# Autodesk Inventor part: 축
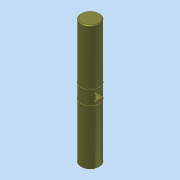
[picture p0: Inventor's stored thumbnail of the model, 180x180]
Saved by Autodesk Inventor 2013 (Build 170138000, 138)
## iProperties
Company: 한국ATC센터
Created: 2015-04
Part Number: 축
Document SubType Name: Modeling
Designer: KYOUNG IL JANG
Density: 7.85 g/cm^3
Material: 강
Author: KYOUNG IL JANG
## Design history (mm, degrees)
sketch "스케치1"
  geometry: C1 r 11 at (0, 0); 1 further point
  constraints: 1 centre point, 1 coincident
  dimensions: "d0" = 22 diameter of C1
extrude "돌출1" new body sketch "스케치1" stored distance "d1" = 150; taper "d2" = 0 deg
sketch "스케치2"
  geometry: L1 (-10.247, -4)-(10.247, -4); L2 (-10.247, 4)-(10.247, 4); A1 r 11 centre (0, 0) between (-10.247, -4) and (10.247, -4) reference; 1 further point
  constraints: 4 end point, 4 point on circle, 2 parallel, 1 horizontal
  dimensions: "d3" = 8 distance between parallel lines of L2 L1
extrude "돌출2" cut sketch "스케치2" stored distance "d4" = 8; taper "d5" = 0 deg
sketch "스케치3"
  geometry: 5 further points
hole "구멍1" sketch "스케치3" at (-4, 4), (4, 4), (4, -4), (-4, -4) diameter "d6" = 2; stored, may be unused: countersink angle "d10" = 90 deg, drill point angle "d12" = 118 deg; dims "d7" = 6, "d8" = 4, "d9" = 2, "d11" = 8
chamfer "모따기1" distance "d13" = 1; stored, may be unused: second distance "d14" = 2, angle "d15" = 45 deg
sketch "스케치4"
  geometry: L1 (-10, 9)-(-11, 9); L2 (-11, 9)-(-11, 7.8); L3 (-11, 7.8)-(-10, 7.8); L4 (-10, 7.8)-(-10, 9); L5 (-10, 75)-(10, 75) reference; L6 (0, -10)-(0, 60) reference; 1 further point
  constraints: 8 end point, 2 parallel, 1 horizontal, 1 perpendicular
  dimensions: "d16" = 7.8 distance from line of L3 point (0, 0); "d17" = 67.2 distance between parallel lines of L3 L5 (derived); "d18" = 11 distance from line of point (0, 0) L2; "d19" = 1 distance of L2.end L3.end; "d20" = 1.2 distance of L1.end L2.end
revolve "회전1" sketch "스케치4" stored, may be unused: angle "d21" = 90 deg
node "솔리드1"
mirror "대칭1"
mirror "대칭2"
